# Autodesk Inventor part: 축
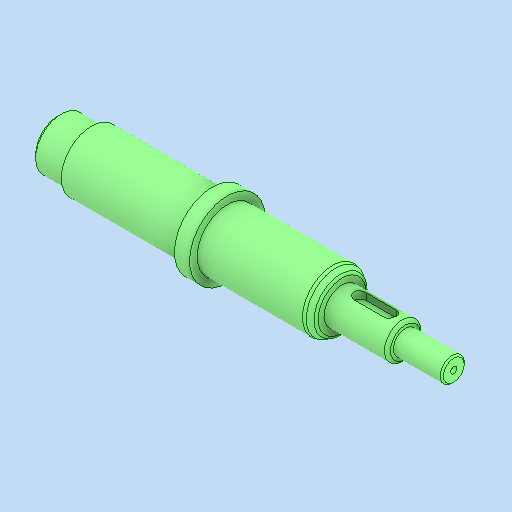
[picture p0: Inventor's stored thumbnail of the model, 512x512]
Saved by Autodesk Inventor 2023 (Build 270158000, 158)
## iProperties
Created: 2024-11
Part Number: 축
Material: 강철, 탄소
Document SubType Name: Modeling
Designer: asung
Density: 7.85 g/cm^3
Appearance: 기본값
Author: jhkim
Sending System: Autodesk Inventor 2025
Preprocessor: ST-DEVELOPER v20
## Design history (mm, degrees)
feature "솔리드1"
node "솔리드2"
